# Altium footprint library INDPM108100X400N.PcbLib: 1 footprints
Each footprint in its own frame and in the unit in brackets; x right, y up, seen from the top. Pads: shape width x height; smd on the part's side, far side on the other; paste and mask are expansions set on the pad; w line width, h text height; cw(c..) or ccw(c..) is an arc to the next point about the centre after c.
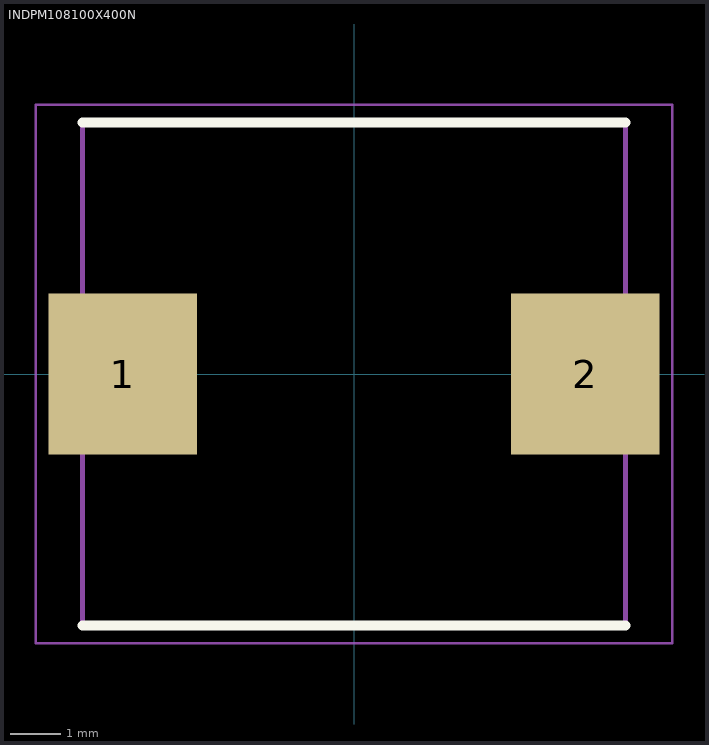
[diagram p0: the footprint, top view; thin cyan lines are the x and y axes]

## INDPM108100X400N [mm]
pads (2):
  rect 2.95x3.2 smd: 1(-4.6,0) 2(4.6,0)
Top Overlay:
  lines w0.2: -5.4,-5 5.4,-5 ; -5.4,5 5.4,5
Mechanical 15:
  lines w0.1: -5.4,-5 5.4,-5 5.4,5 -5.4,5 -5.4,-5
Mechanical 20:
  lines w0.05: -6.325,-5.35 6.325,-5.35 6.325,5.35 -6.325,5.35 -6.325,-5.35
